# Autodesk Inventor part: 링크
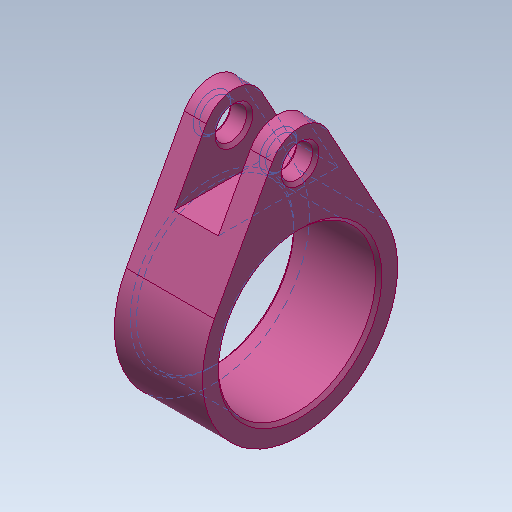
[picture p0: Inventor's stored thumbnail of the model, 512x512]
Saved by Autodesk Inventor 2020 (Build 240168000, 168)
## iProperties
Created: 2016-02
Part Number: 링크
Material: 강철, 연강
Document SubType Name: Modeling
Designer: test
Density: 1 g/cm^3
Appearance: 분홍색
Author: test
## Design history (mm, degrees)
sketch "스케치1"
  geometry: L1 (24.386, 4.394)-(7.398, 13.621); L2 (24.386, -4.394)-(7.398, -13.621); A1 r 15.5 centre (0, 0) between (7.398, 13.621) and (7.398, -13.621); A2 r 5 centre (22, 0) between (24.386, -4.394) and (24.386, 4.394); 1 further point
  constraints: 4 end point, 4 point on circle, 4 tangent, 2 centre point, 1 coincident, 1 horizontal alignment
  dimensions: "d0" = 22 distance of point (0, 0) A2.centre; "d1" = 15.5 radius of A1; "d2" = 5 radius of A2
extrude "돌출1" new body sketch "스케치1" stored distance "d3" = 14; taper "d4" = 0 deg
sketch "스케치2"
  geometry: C1 r 12.5 at (0, 0); 1 further point
  constraints: 1 centre point, 1 coincident
  dimensions: "d5" = 25 diameter of C1
extrude "돌출2" cut sketch "스케치2" extent not by distance; stored distance "d6" = 14; taper "d7" = 0 deg
sketch "스케치3"
  geometry: C1 r 2.5 at (22, 0); A1 r 5 centre (22, 0) between (24.386, -4.394) and (24.386, 4.394) reference; 1 further point
  constraints: 1 centre point, 1 coincident
  dimensions: "d8" = 5 diameter of C1
extrude "돌출3" cut sketch "스케치3" extent not by distance; stored distance "d9" = 14; taper "d10" = 0 deg
sketch "스케치4"
  geometry: L1 (24.386, -4.394)-(7.398, -13.621) reference; L2 (7.398, 13.621)-(24.386, 4.394) reference; L3 (15, 9.492)-(15, -9.492); C1 r 2.5 at (22, 0) reference; C2 r 12.5 at (0, 0) reference; A1 r 15.5 centre (0, 0) between (7.398, 13.621) and (7.398, -13.621) reference; A2 r 5 centre (22, 0) between (24.386, -4.394) and (24.386, 4.394) reference; 1 further point
  constraints: 2 end point, 2 point on line, 1 vertical
  dimensions: "d11" = 15 distance from line of L3 point (0, 0)
extrude "돌출4" cut sketch "스케치4" stored distance "d12" = 7; taper "d13" = 0 deg
chamfer "모따기1" distance "d14" = 0.5; stored, may be unused: second distance "d15" = 2, angle "d16" = 45 deg
node "솔리드1"
node "절단 모서리 투영1"
